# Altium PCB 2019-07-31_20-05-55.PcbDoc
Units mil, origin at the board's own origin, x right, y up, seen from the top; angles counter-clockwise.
Board outline 3200 x 1600 mil, 4 copper layers (Top Layer, MidLayer1, MidLayer2, Bottom Layer); 20 components, 11 nets, 51 pads, 32 vias.
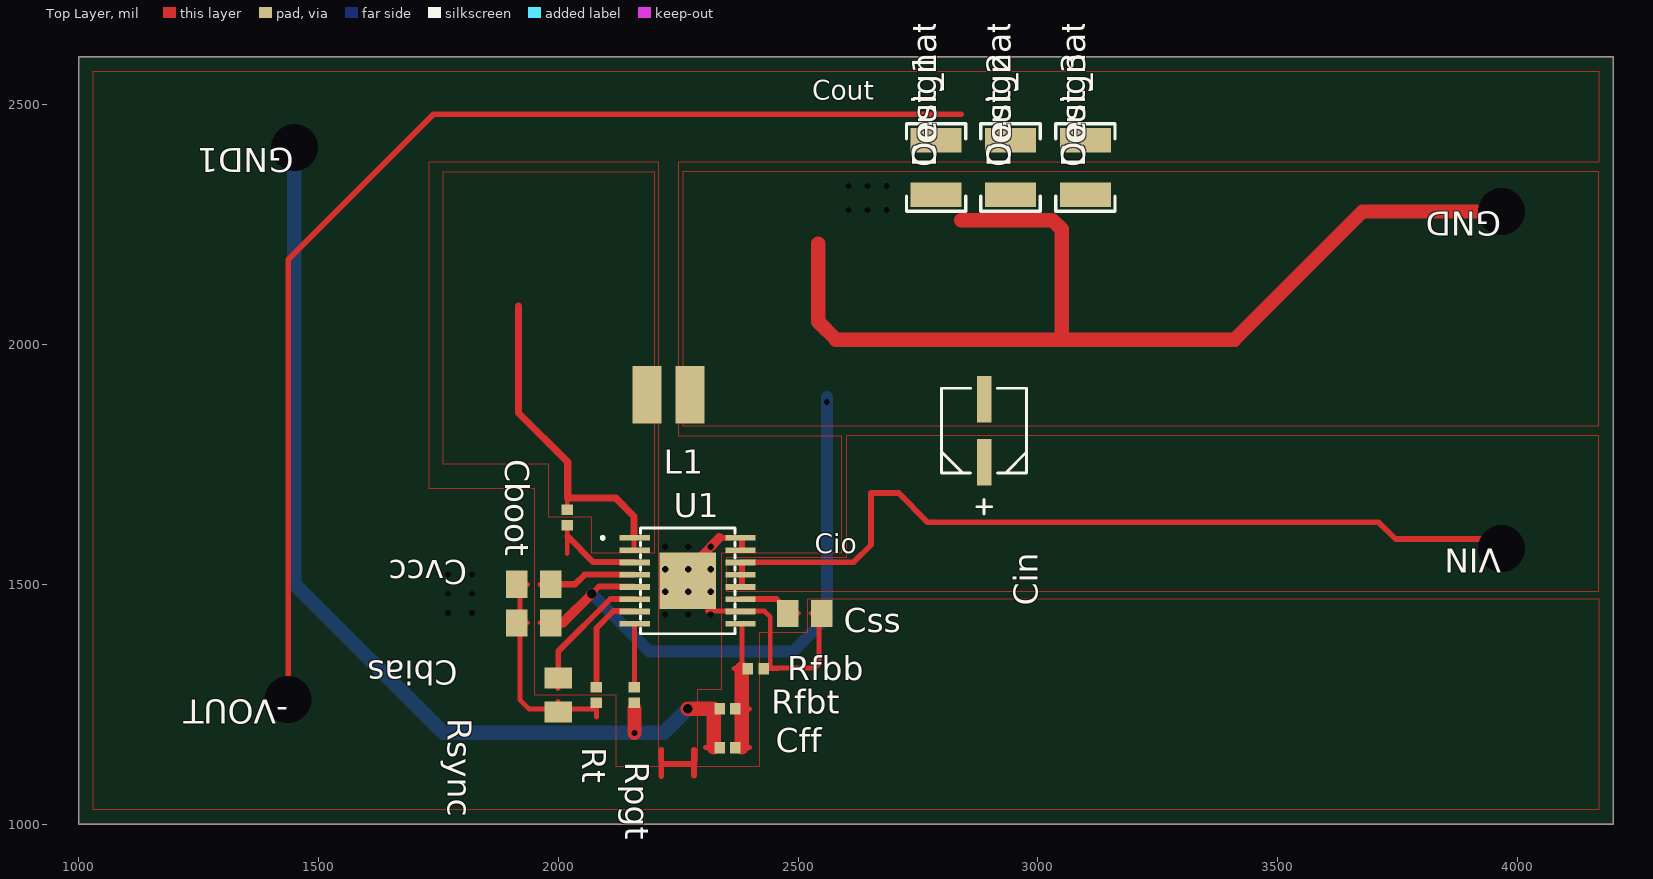
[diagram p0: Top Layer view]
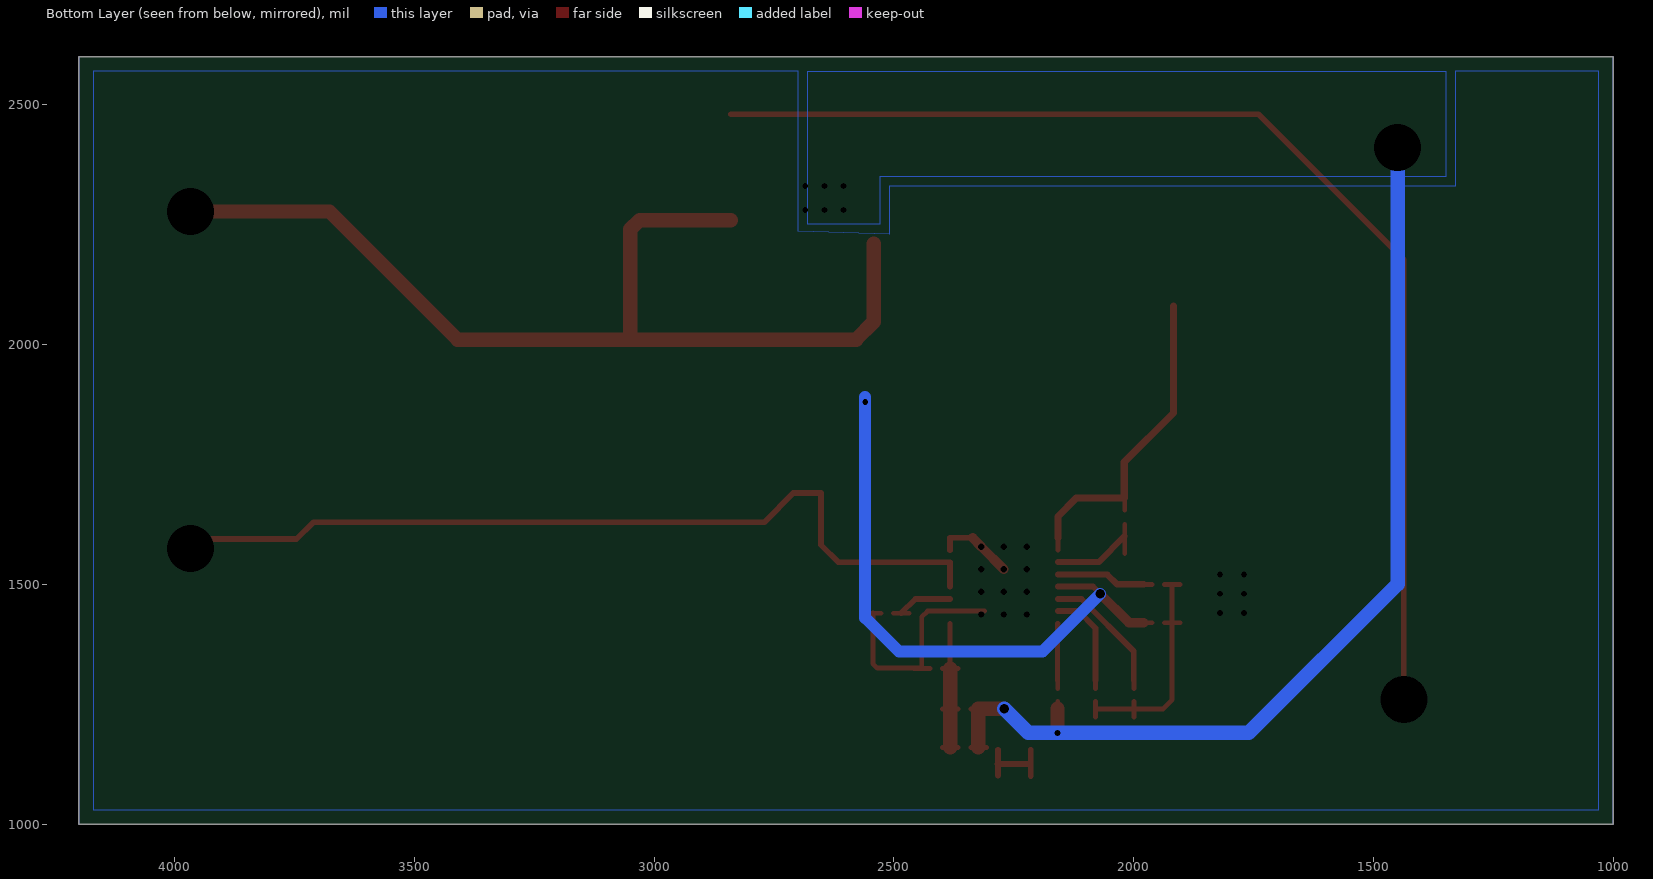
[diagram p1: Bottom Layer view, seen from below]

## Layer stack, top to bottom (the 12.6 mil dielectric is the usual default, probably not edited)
Top Layer: signal copper 1.4
Dielectric: core 12.6, FR-4, Dk 4.8
MidLayer1: signal copper 1.4
Dielectric: prepreg 12.6, FR-4, Dk 4.8
MidLayer2: signal copper 1.4
Dielectric: core 12.6, FR-4, Dk 4.8
Bottom Layer: signal copper 1.4

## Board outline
1000,1000 4200,1000 4200,2600 1000,2600

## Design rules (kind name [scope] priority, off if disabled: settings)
PlaneConnect [All] p0: scope1count=1 scope1_0_kind=Board scope1_0_value=Board scope2count=1 scope2_0_kind=Board scope2_0_value=Board commentlength=0 planeconnectstyle=Direct reliefexpansion=20 reliefentries=4 reliefconductorwidth=10 reliefairgap=10
PlaneConnect [All] p1: planeconnectstyle=Direct reliefexpansion=20 reliefentries=4 reliefconductorwidth=10 reliefairgap=10
PolygonConnect [All] p0: scope1count=1 scope1_0_kind=Board scope1_0_value=Board scope2count=1 scope2_0_kind=Board scope2_0_value=Board commentlength=0 connectstyle=Direct reliefconductorwidth=10 reliefentries=4 polygonreliefangle="90 Angle"
PolygonConnect [All] p1: connectstyle=Direct reliefconductorwidth=10 reliefentries=4 polygonreliefangle="90 Angle"

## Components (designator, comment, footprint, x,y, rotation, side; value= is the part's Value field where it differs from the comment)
-VOUT "" TP-1502 1437,1259 r180 top
Cbias "" 0805 1949,1419 r180 top
Cboot "" 0402 2019,1639 r270 top
Cff "" 0402 2353,1159 r0 top
Cin "" SM_RADIAL_B 2888,1820 r90 top
Cout_1 "" 1210_270 2788,2369 r90 top
Cout_2 "" 1210_270 2943,2369 r90 top
Cout_3 "" 1210_270 3099,2369 r90 top
Css "" 0805 2514,1439 r0 top
Cvcc "" 0805 1949,1500 r180 top
GND "" TP-1502 3966,2277 r180 top
GND1 "" TP-1502 1449,2409 r180 top
L1 "" ME3220 2230,1895 r0 top
Rfbb "" 0402 2412,1324 r0 top
Rfbt "" 0402 2353,1240 r0 top
Rpgt "" 0402 2159,1269 r270 top
Rsync "" 0805 2000,1269 r270 top
Rt "" 0402 2079,1269 r270 top
U1 "" PWP0016F 2270,1507 r0 top
VIN "" TP-1502 3966,1574 r180 top

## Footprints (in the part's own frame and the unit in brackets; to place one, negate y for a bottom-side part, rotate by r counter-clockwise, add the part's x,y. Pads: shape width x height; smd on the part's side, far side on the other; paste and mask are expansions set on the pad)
0402 [mil]
  rect 22x24 smd: 1(-16.5,0) 2(16.5,0)
0805 [mil]
  rect 44x57 smd: 1(-35.5,0) 2(35.5,0)
1210_270 [mm]
  rect 1.3x2.7 smd: 1(-1.45,0) 2(1.45,0)
  silkscreen extent -2.32,-1.57 2.32,1.57
ME3220 [mil]
  rect 60x120 smd: 1(-45,0) 2(45,0)
PWP0016F [mm]
  rect 1.6x0.3 smd: 1(-2.8,2.275) 2(-2.8,1.625) 3(-2.8,0.975) 4(-2.8,0.325) 5(-2.8,-0.325) 6(-2.8,-0.975) 7(-2.8,-1.625) 8(-2.8,-2.275) 9(2.8,-2.275) 10(2.8,-1.625) 11(2.8,-0.975) 12(2.8,-0.325) 13(2.8,0.325) 14(2.8,0.975) 15(2.8,1.625) 16(2.8,2.275)
  rect 3x3 smd: 17(0,0)
  silkscreen extent -4.58,-2.8 2.5,2.8
SM_RADIAL_B [mil]
  rect 97x30 smd: 1(-66,0) 2(66,0)
  silkscreen extent -174,-88 88,88
TP-1502 [mil]
  round 65 / inner round 0 / far side round 65 hole 32: 1(0,0)

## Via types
v1: diameter 0, hole 12, Top Layer to Bottom Layer, 14 vias
v2: diameter 0, hole 13, Top Layer to Bottom Layer, 12 vias
v3: diameter 0, hole 98, Top Layer to Bottom Layer, 4 vias
v4: diameter 0, hole 20, Top Layer to Bottom Layer, 2 vias

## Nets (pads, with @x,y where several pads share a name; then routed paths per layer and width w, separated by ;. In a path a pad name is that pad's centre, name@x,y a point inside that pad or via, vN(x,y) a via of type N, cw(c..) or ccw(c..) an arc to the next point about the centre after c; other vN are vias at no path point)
0: -VOUT.1 Cbias.2 Cout_1.2 Cout_2.2 Cout_3.2 Css.2 Cvcc.2 Rfbb.2 Rsync.2 Rt.2 U1.10 U1.15 U1.16 U1.17 | length 3851.7
  Top Layer w10: Cbias.2@1903,1419.5 1936,1419.5 ; Cvcc.2@1903,1499.5 1936,1499.5 ; Cvcc.2@1920,1500 1920,1420 1920,1259 1939,1240 2000,1240 2080,1240 ; Rsync.2@1999.5,1223 1999.5,1256 ; 2079.5,1223 Rt.2@2079.5,1256 ; 2311,1444 2383,1444 2430,1444 2442,1432 2442,1325 2535,1325 2544,1334 Css.2@2544,1440 ; Rfbb.2@2425,1324.5 2458,1324.5 ; 2527,1439.5 Css.2@2560,1439.5
  Top Layer w12: v3(1437,1260) 1437,2177 1740,2480 2840,2480 ; 2215,1100 2215,1125 ; 2215,1155 2215,1125 ; 2283,1101 2283,1125 ; 2283,1155 2283,1125 ; 2336,1597 2383,1597 U1.15@2383,1571 ; 2215,1125 2283,1125 ; 2283,1125 2284,1125 2283,1125
  Top Layer w20: v2(2271,1531) v2(2318,1578) 2336,1597
  other v1: 1770,1440 1820,1440 1770,1480 1820,1480 1770,1520 1820,1520
  other v2: 2223,1437 2271,1437 2318,1437 2223,1484 2271,1484 2318,1484 2223,1531 2318,1531 2223,1578 2271,1578
2: Cin.1 U1.12 U1.13 U1.14 VIN.1 | length 1797.7
  Top Layer w12: U1.12@2383,1495 2383,1520 2383,1546 2616,1546 2652,1582 2652,1690 2710,1690 2770,1629 3010,1629 3710,1629 3746,1594 VIN.1@3967,1594
  other v3: 3967,1574
6: Cff.2 Rfbb.1 Rfbt.2 U1.9 | length 356
  Top Layer w10: Cff.2@2366,1159.5 2399,1159.5 ; Rfbt.2@2366,1239.5 2399,1239.5 ; 2366,1324.5 Rfbb.1@2399,1324.5 ; 2383,1325 U1.9@2383,1418
  Top Layer w30: 2383,1160 2383,1240 2383,1324
8: Cbias.1 Cff.1 Cin.2 Cout_1.1 Cout_2.1 Cout_3.1 GND1.1 GND.1 L1.2 Rfbt.1 Rpgt.2 U1.5 | length 5595.4
  Top Layer w10: 1962,1419.5 Cbias.1@1995,1419.5 ; 2158.5,1223 Rpgt.2@2158.5,1256 ; 2307,1159.5 Cff.1@2340,1159.5 ; 2307,1239.5 Rfbt.1@2340,1239.5
  Top Layer w12: v4(2070,1480) 2085,1495 U1.5@2158,1495
  Top Layer w20: Cbias.1@1979,1420 2010,1420 v4(2070,1480)
  Top Layer w30: v1(2159,1190) 2159,1240 ; v4(2270,1240) 2324,1240 2324,1160 ; 2542,2210 2542,2047 2579,2010 3050,2010 ; 2840,2259 3030,2259 3050,2240 3050,2010 ; v3(3967,2277) 3677,2277 3410,2010 3050,2010
  Bottom Layer w25: v4(2070,1480) 2190,1360 2490,1360 2560,1430 2560,1890
  Bottom Layer w30: v3(1450,2410) 1450,1500 1760,1190 v1(2159,1190) 2220,1190 v4(2270,1240)
  other v1: 2560,1880 2605,2280 2645,2280 2685,2280 2605,2330 2645,2330 2685,2330
9: Cboot.1 L1.1 U1.1 U1.2 | length 728.4
  Top Layer w10: Cboot.1@2019,1654 2019,1715 ; U1.2@2158,1571 U1.1@2158,1597
  Top Layer w15: 1917,2080 1917,1857 2020,1755 2020,1680 2120,1680 2158,1641 U1.1@2158,1597
10: Rsync.1 U1.6 | length 297.1
  Top Layer w10: 1999.5,1282 Rsync.1@1999.5,1315
  Top Layer w12: Rsync.1@2000,1299 2000,1360 2109,1469 U1.6@2158,1469
11: Rt.1 U1.7 | length 235.2
  Top Layer w10: Rt.1@2079.5,1282 2079.5,1315
  Top Layer w12: 2080,1299 2080,1408 2115,1444 U1.7@2158,1444
13: Cvcc.1 U1.4 | length 220.3
  Top Layer w10: 1962,1499.5 Cvcc.1@1995,1499.5
  Top Layer w13: Cvcc.1@1979,1500 2035,1500 2055,1520 U1.4@2158,1520
15: Css.1 U1.11 | length 146.7
  Top Layer w10: Css.1@2468,1439.5 2501,1439.5
  Top Layer w12: U1.11@2383,1469 2455,1469 Css.1@2485,1440
17: Cboot.2 U1.3 | length 221.7
  Top Layer w10: 2019,1564 Cboot.2@2019,1625
  Top Layer w13: 2020,1600 2073,1546 U1.3@2158,1546
20: Rpgt.1 U1.8 | length 153
  Top Layer w10: U1.8@2158,1418 2159,1418 2159,1299 ; Rpgt.1@2158.5,1282 2158.5,1315

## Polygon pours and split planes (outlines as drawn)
9 on Top Layer " " (solid, pour order 1): 2200,2360 2200,1565 2070,1565 2070,1640 1980,1640 1980,1750 1760,1750 1760,2360
2 on Top Layer " " (solid, pour order 2): 4170,1485 4170,1810 2600,1810 2600,1555 2350,1555 2350,1485
8 on Top Layer " " (solid, pour order 3): 2260,2360 2260,1830 4170,1830 4170,2360
0 on Top Layer " " (solid, pour order 7): 1030,2570 4170,2570 4170,2380 2250,2380 2250,1810 2590,1810 2590,1565 2340,1565 2340,1280 2290,1280 2290,1130 2210,1130 2210,2380 1730,2380 1730,1700 1950,1700 1950,1270 2120,1270 2120,1120 2420,1120 2420,1400 2520,1400 2520,1470 4170,1470 4170,1030 1030,1030
8 on Bottom Layer " " (solid, pour order 0): 2530,2250 2680,2250 2680,2570 1350,2570 1350,2350 2530,2350
0 on Bottom Layer " " (solid, pour order 6): 1030,2570 1330,2570 1330,2330 2510,2330 2510,2230 2700,2236 2700,2570 4170,2570 4170,1030 1030,1030
0 on MidLayer2 " " (solid, pour order 4): 1030,2570 1030,1030 4170,1030 4170,2570
0 on MidLayer1 " " (solid, pour order 5): 1030,2570 4170,2570 4170,1030 1030,1030
no net on Top Paste "Top Layer-No Net" (solid, remove dead copper): 2129.25,1422.36 2129.25,1412.51 2190.28,1412.51 2190.28,1422.36
no net on Top Paste "Top Layer-No Net" (solid, remove dead copper): 2349.72,1422.36 2349.72,1412.51 2410.75,1412.51 2410.75,1422.36
no net on Top Paste "Top Layer-No Net" (solid, remove dead copper): 2349.72,1447.95 2349.72,1438.1 2410.75,1438.1 2410.75,1447.95
no net on Top Paste "Top Layer-No Net" (solid, remove dead copper): 2349.72,1473.54 2349.72,1463.69 2410.75,1463.69 2410.75,1473.54
no net on Top Paste "Top Layer-No Net" (solid, remove dead copper): 2349.72,1499.13 2349.72,1489.28 2410.75,1489.28 2410.75,1499.13
no net on Top Paste "Top Layer-No Net" (solid, remove dead copper): 2349.72,1524.72 2349.72,1514.87 2410.75,1514.87 2410.75,1524.72
no net on Top Paste "Top Layer-No Net" (solid, remove dead copper): 2349.72,1550.31 2349.72,1540.46 2410.75,1540.46 2410.75,1550.31
no net on Top Paste "Top Layer-No Net" (solid, remove dead copper): 2349.72,1575.9 2349.72,1566.05 2410.75,1566.05 2410.75,1575.9
no net on Top Paste "Top Layer-No Net" (solid, remove dead copper): 2349.72,1601.49 2349.72,1591.64 2410.75,1591.64 2410.75,1601.49
no net on Top Solder "Top Layer-No Net" (solid, remove dead copper): 2128.27,1602.47 2128.27,1590.66 2191.26,1590.66 2191.26,1602.47
no net on Top Solder "Top Layer-No Net" (solid, remove dead copper): 2128.27,1576.88 2128.27,1565.07 2191.26,1565.07 2191.26,1576.88
no net on Top Solder "Top Layer-No Net" (solid, remove dead copper): 2128.27,1551.29 2128.27,1539.48 2191.26,1539.48 2191.26,1551.29
no net on Top Solder "Top Layer-No Net" (solid, remove dead copper): 2128.27,1525.7 2128.27,1513.89 2191.26,1513.89 2191.26,1525.7
no net on Top Solder "Top Layer-No Net" (solid, remove dead copper): 2128.27,1500.11 2128.27,1488.3 2191.26,1488.3 2191.26,1500.11
no net on Top Solder "Top Layer-No Net" (solid, remove dead copper): 2128.27,1474.52 2128.27,1462.71 2191.26,1462.71 2191.26,1474.52
no net on Top Solder "Top Layer-No Net" (solid, remove dead copper): 2128.27,1448.93 2128.27,1437.12 2191.26,1437.12 2191.26,1448.93
no net on Top Solder "Top Layer-No Net" (solid, remove dead copper): 2128.27,1423.34 2128.27,1411.53 2191.26,1411.53 2191.26,1423.34
no net on Top Solder "Top Layer-No Net" (solid, remove dead copper): 2348.74,1423.34 2348.74,1411.53 2411.73,1411.53 2411.73,1423.34
no net on Top Solder "Top Layer-No Net" (solid, remove dead copper): 2348.74,1448.93 2348.74,1437.12 2411.73,1437.12 2411.73,1448.93
no net on Top Solder "Top Layer-No Net" (solid, remove dead copper): 2348.74,1474.52 2348.74,1462.71 2411.73,1462.71 2411.73,1474.52
no net on Top Solder "Top Layer-No Net" (solid, remove dead copper): 2348.74,1500.11 2348.74,1488.3 2411.73,1488.3 2411.73,1500.11
no net on Top Solder "Top Layer-No Net" (solid, remove dead copper): 2348.74,1525.7 2348.74,1513.89 2411.73,1513.89 2411.73,1525.7
no net on Top Solder "Top Layer-No Net" (solid, remove dead copper): 2348.74,1551.29 2348.74,1539.48 2411.73,1539.48 2411.73,1551.29
no net on Top Solder "Top Layer-No Net" (solid, remove dead copper): 2348.74,1576.88 2348.74,1565.07 2411.73,1565.07 2411.73,1576.88
no net on Top Solder "Top Layer-No Net" (solid, remove dead copper): 2348.74,1602.47 2348.74,1590.66 2411.73,1590.66 2411.73,1602.47
no net on Top Paste "Top Layer-No Net" (solid, remove dead copper): 2214.88,1562.12 2214.88,1510.94 2266.06,1510.94 2266.06,1562.12
no net on Top Paste "Top Layer-No Net" (solid, remove dead copper): 2214.88,1503.06 2214.88,1451.88 2266.06,1451.88 2266.06,1503.06
no net on Top Paste "Top Layer-No Net" (solid, remove dead copper): 2273.94,1562.12 2273.94,1510.94 2325.12,1510.94 2325.12,1562.12
no net on Top Paste "Top Layer-No Net" (solid, remove dead copper): 2273.94,1503.06 2273.94,1451.88 2325.12,1451.88 2325.12,1503.06
no net on Top Layer "Top Layer-No Net" (solid, remove dead copper): 2270,1566.06
no net on Top Layer "Top Layer-No Net" (solid, remove dead copper): 2270,1447.94
no net on Top Solder "Top Layer-No Net" (solid, remove dead copper): 2270,1566.06
no net on Top Solder "Top Layer-No Net" (solid, remove dead copper): 2270,1447.94

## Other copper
Multi-Layer:
  the board outline again, w1

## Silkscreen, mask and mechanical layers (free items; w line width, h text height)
Top Overlay:
  text "Cout" at 2530,2510 h40
  text "Cio" at 2535,1565 h40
